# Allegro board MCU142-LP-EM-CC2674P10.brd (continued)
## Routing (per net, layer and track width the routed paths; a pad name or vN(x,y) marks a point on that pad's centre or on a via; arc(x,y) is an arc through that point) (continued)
XDS_BOARDID_SCL: length 16.1
  TOP w0.15: v1(11.83,80.05) U3.1
  L3 w0.15: v1(11.83,80.05) 19.88,80.05 22.84,83.01 J3.15
XDS_BOARDID_SDA: length 10.6
  TOP w0.15: U3.3 v1(13.73,80.86)
  L3 w0.15: v1(13.73,80.86) 18.26,80.86 20.3,82.9 J3.17
N3100073: length 1.4
  TOP w0.3: L14.1 C22.2 L13.2
N3100081: length 1.8
  TOP w0.3: C13.2 26.66,38.5 C23.2 26.66,38.98 26.66,38.98 L14.2
N3100583: length 9.2
  TOP w0.3: Z66.1 v1(27.25,34.5) ; v1(27.25,29.03) CR1.2 C15.2
  L2 w0.2: v1(27.25,34.5) v1(27.25,29.03)
N3100745: length 9.1
  TOP w0.15: C81.1 34.69,40.31 Y1.1 34,40.6 32.41,42.19 32.41,43.04 30.17,45.28 U1.8
N3100801: length 7
  TOP w0.15: C82.1 34.7,43.4 Y1.2 32.87,43.1 30.67,45.29 U1.9
N3100989: length 3.5
  TOP w0.25: C53.1 29.66,43.32 L53.2 29.14,43.85 L52.1 28.67,44.34 U1.5
N3100993: length 4.2
  TOP w0.3: Z61.1 Z60.2 27.26,22.04 27.25,22.05 C16.1
N3100997: length 3.1
  TOP w0.25: U1.6 29.17,44.63 L52.2 29.54,44.27 C61.1 30.12,43.72 L62.1
N3101171: length 1.5
  TOP w0.3: U1.23 33.4,51.45 33.88,51.93 C79.1
N3101223: length 6
  TOP w0.15: U1.47 25.1,46.95 24.92,46.78 22.68,46.78 21.48,45.57 C83.1 21.46,45.57
  TOP w0.3: Y2.1 21.46,45.57
N3101429: length 2.2
  TOP w0.3: A1.1 27.27,19.7 27.26,19.71 Z62.2 Z61.2
N3101449: length 6.8
  TOP w0.15: 20.81,48.09 Y2.3 21.44,48.53 21.85,48.53 23.3,47.07 24.75,47.07 25.13,47.45 U1.46
  TOP w0.3: C84.1 20.81,48.09
N3109742: length 12.7
  TOP w0.15: R71.2 19.15,53.05 19.62,53.05 v1(19.82,52.85)
  BOTTOM w0.15: v1(19.82,52.85) 18.52,51.55 11.6,51.55 10.39,52.76 J1.12
N3109836: length 12.3
  TOP w0.15: v1(19.92,50.85) 19.88,50.8 19.52,50.8 R72.2
  BOTTOM w0.15: J1.14 19.29,50.22 v1(19.92,50.85)
N3109894: length 22.9
  TOP w0.15: J2.13 47.33,52.42 47.33,63.15 44.98,65.5 40.42,65.5 39.57,66.35 R46.1
N3109960: length 25.8
  TOP w0.15: J2.15 46.46,50.75 46.46,59.71 46.45,59.72 46.45,62.16 43.41,65.2 39.27,65.2 38.12,66.35 R47.1
N3110034: length 29.1
  TOP w0.15: R48.1 36.67,66.35 38.2,64.82 42.38,64.82 44.7,62.5 44.7,62.48 45.67,61.51 45.67,60.41 45.59,60.32 45.59,49.08 J2.17
N3110086: length 32.1
  TOP w0.15: R49.1 35.22,66.35 37.58,63.99 41.63,63.99 44.34,61.28 44.34,47.79 J2.19
N3110356: length 2.9
  TOP w0.15: R14.2 9.55,35.93 P3.1
N3110380: length 2.9
  TOP w0.15: P3.3 15.8,36.01 R15.2
N3110768: length 1.4
  TOP w0.15: R56.1 SW1.4
N3110772: length 4.1
  TOP w0.15: SW2.3 54.4,70.18 54.55,70.03 54.55,68 55.45,67.1 R55.1
N3110876: length 1.8
  TOP w0.15: R15.1 14.63,34.75 14.63,34.75 CR3.2
N3110880: length 1.9
  TOP w0.15: CR2.2 10.87,34.75 10.87,34.75 R14.1
N3111246: length 1.9
  TOP w0.3: R12.1 45,40 C30.1 U4.8
N3111262: length 0.9
  TOP w0.15: R60.1 U4.7
N3111266: length 2.1
  TOP w0.15: R59.1 47.05,36.37 47.85,37.17 U4.3
N3215956: length 2.7
  TOP w0.15: 26.35,43.2 26.33,43.19
  TOP w0.25: U1.1 26.67,45.35 26.35,45.03 L11.1 L12.1 26.35,43.2 ; 26.33,43.19 C12.1
N3215974: length 2.7
  TOP w0.25: U1.2 27.17,45.25 26.91,44.99 L11.2 26.91,43.89 C21.2 26.92,43.88 L21.1
N3221205: length 1.3
  TOP w0.25: L21.2 26.92,42.53 26.65,42.25 26.65,42.2 ; 26.65,42.2 26.65,41.97 ; 26.65,42.2 26.32,42.52 C12.2
  TOP w0.3: L13.1 26.65,41.97
N3221963: length 0.9
  TOP w0.15: U2.3 27.3,37.07 27.29,37.07
  TOP w0.3: 27.29,37.07 C13.1
N3527855: length 14.3
  TOP w0.25: v1(28.54,42.41) 29.06,42.94 L53.1 29.8,42.4 29.82,42.4 30.3,41.91 C52.1
  TOP w0.3: v1(20.15,41.32) R7.1
  L3 w0.3: v1(20.15,41.32) 21.3,41.32 22.03,40.6 23.22,40.6 24.14,39.68 27.72,39.68 28.01,39.96 28.01,41.11 28.35,41.45 28.35,42.1 28.54,42.29 v1(28.54,42.41)
N3527991: length 2.7
  TOP w0.25: 31.2,41.02 L54.1 ; 30.54,42.44 30.73,42.25 31.2,42.25 ; 31.2,42.25 C62.1 ; 31.2,42.25 31.2,42.65 30.98,42.87 30.97,42.87
  TOP w0.3: C62.1 31.2,41.02
N3528063: length 1.4
  TOP w0.25: 31.2,39.78 C63.1
  TOP w0.3: C63.1 L55.1 ; L54.2 31.2,39.78
N3528075: length 1.4
  TOP w0.3: L55.2 C64.1 C56.1
N3806444: length 7.4
  TOP w0.3: C15.1 P5.1
N3819473: length 0.6
  TOP w0.3: C56.2 30.63,37.08 Z63-2.1
N3819482: length 1.2
  TOP w0.15: U2.1 28.55,37.07
  TOP w0.3: 28.55,37.07 Z64.2 29.44,37.07 Z63-2.2
N3821368: length 1.1
  TOP w0.15: U2.5 27.92,36.12 Z65.2
  TOP w0.3: Z65.2 Z66.2

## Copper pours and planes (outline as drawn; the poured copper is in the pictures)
GND on TOP (solid shape): 24.39,17.4 25.59,17.4 25.59,18.14 26.59,18.14 26.59,16.11 18.59,16.11 18.59,13.44 24.39,13.44 24.39,14.24 23.39,14.24 23.39,15.45 26.52,15.45 27.04,16.21 27.04,18.14 27.5,18.14 27.5,16.06 26.59,14.74 26.59,14.24 25.59,14.24 25.59,12.44 41.99,12.44 41.99,11.23 16.41,11.23 16.41,17.4 23.39,17.4 23.39,18.14 24.39,18.14
GND on TOP (solid shape): 9.45,81.1 9.45,76.1 3.2,76.1 3.07,76.44 2.75,76.6 2.15,76.6 1.83,76.44 1.7,76.1 1.25,76.1 0.69,77.29 0.5,78.6 0.5,81.1
GND on BOTTOM (solid shape): 9.45,76.1 1.25,76.1 0.69,77.3 0.5,78.6 0.5,81.1 9.45,81.1
GND on TOP: 57,88.63 57.71,88.34 58,87.63 58,78.6 57.74,77.1 57.01,75.76 55.8,72.3 57.01,68.84 57.74,67.5 58,66 58,19.65 57.56,18.59 56.5,18.15 2,18.15 0.94,18.59 0.5,19.65 0.5,66 0.76,67.5 1.49,68.84 2.7,72.3 1.49,75.76 0.76,77.1 0.5,78.6 0.5,87.63 0.79,88.34 1.5,88.63 ; 17 cut-outs
GND on BOTTOM: 56.95,88.62 57.66,88.33 57.95,87.62 57.95,77.93 57.62,76.79 57.01,75.76 55.8,72.3 57.01,68.84 57.62,67.81 57.95,66.67 57.95,19.65 57.51,18.59 56.45,18.15 2,18.15 0.94,18.59 0.5,19.65 0.5,66 0.76,67.5 1.49,68.84 2.7,72.3 1.49,75.76 0.76,77.1 0.5,78.6 0.5,87.62 0.79,88.33 1.5,88.62 ; 2 cut-outs
GND on L2: 0.5,87.65 0.79,88.36 1.5,88.65 57,88.65 57.71,88.36 58,87.65 58,78.6 57.74,77.1 57.01,75.76 55.8,72.3 57.01,68.84 57.74,67.5 58,66 58,19.65 57.56,18.59 56.5,18.15 2,18.15 0.94,18.59 0.5,19.65 0.5,66 0.76,67.5 1.49,68.84 2.7,72.3 1.49,75.76 0.76,77.1 0.5,78.6 ; 2 cut-outs
GND on L3: 2,18.15 0.94,18.59 0.5,19.65 0.5,66 0.76,67.5 1.49,68.84 2.49,70.8 2.66,73 55.84,73 56.01,70.8 57.01,68.84 57.74,67.5 58,66 58,19.65 57.56,18.59 56.5,18.15 ; 9 cut-outs
VDDR on TOP: 26.62,57.6 28.82,57.6 29.62,56.8 29.62,55.65 27.95,55.65 27.7,55.4 27.45,55.4 27,55.85 27,56.3 27,56.3 26.62,56.67
VDDR on L3: 24.75,46 24.75,48.81 23.55,48.81 23.55,54.55 27.88,54.55 27.88,57.68 25.15,57.68 25.15,57.12 23.94,56.15 21.96,56.15 21.96,46
VDDS on TOP: 23.61,55.38 23.61,53.62 25,53.62 25,55.38
VDDS on TOP: 23.61,54.7 23.61,53.62 26.9,53.62 26.9,54.7
VDDS on L3: 23.62,54.4 23.62,48.94 25.65,48.94 25.65,54.4
WMCU_VDD on TOP: 23.02,57.55 23.02,55.73 25,55.73 25,57.55
WMCU_VDD on L3: 23.45,64.4 15.47,72.2 7.71,72.2 7.71,64.81 7,64.1 5.63,64.1 4.94,64.82 5.06,68.01 4.99,74.45 5,74.45 5,76.45 21.6,76.45 21.6,88.4 26.65,88.4 26.65,76.4 54.87,76.4 54.87,32.85 54.84,32.82 53.85,32.82 52.45,31.43 51.5,31.43 50.1,32.82 50.1,33.7 53.15,33.7 53.15,72.2 41.11,72.2 41.11,70.4 39.71,70.4 39.71,72.2 20.68,72.2 21.05,71.8 21.65,71.2 25,67.76 25,55.72 23.02,55.72 23.02,57.75 23.45,57.75 ; 1 cut-out

Small or netless copper shapes (teardrops, artwork), in the pictures only: 76 on TOP, 60 on BOTTOM, 50 on L3

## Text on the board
Ref Des/Silkscreen Bottom: J1 | 1 | 10 | 21 | 30 | J3 | J4 | 31 | 40 | 11 | 20 | J2 | DIO23 | DIO22 | DIO24 | DIO12 | DIO13 | DIO25 | DIO27 | DIO28 | DIO29 | DIO30 | DIO26 | DIO7 | DIO6 | DIO20 | DIO18 | BPRST | DIO9 | DIO8 | DIO19 | DIO11 | LPRST | DIO15 | DIO14 | DIO10 | DIO5 | DIO21 | TMS | TCK | DIO16 | DIO17
User.Comments: MCU142 | Rev. A | Milling tool 2.0 mm TYP | Rev | A | RTM Version | Description | Revisions | RED | AFTER THE PRESS | BOTTOM LAYER | 2024-12-05 | Date
Ref Des/Silkscreen Top: U3 | U1 | CR4 | J3 | P4 | U4 | J1 | 10 | 1 | 21 | 30 | J4 | 40 | 31 | 20 | 11 | J2 | DIO23 | DIO12 | DIO13 | DIO22 | DIO24 | DIO15 | BTN-1 | Red: | DIO6 | DIO25 | DIO26 | DIO27 | DIO28 | DIO29 | DIO30 | LEDs | Green: | DIO7 | Rx/Tx | CC-ANTENNA-DK | Mount for: | PA | Target In | LP-EM-CC2674P10 | Rev:A | DIO20 | DIO18 | BPRST | BTN-2 | DIO14 | MCU142 | DIO19 | DIO11 | LPRST | DIO9 | DIO8 | DIO21 | DIO5 | DIO10 | DIO16 | DIO17 | TMS | TCK | GND | 5V | 3V3 | RXD | TXD | SWO | nRST | TDO | TDI
XSECTION_CHART: L1: TOP CONDUCTOR - COPPER + PLATING 0.035 MM | *  DIELECTRIC - FR-4 0.175 MM (TOP PRIORITY) | L2: L2 PLANE - COPPER 0.035 MM | *  DIELECTRIC - FR-4 1.11 MM | L3: L3 PLANE - COPPER 0.035 MM | *  DIELECTRIC - FR-4 0.175 MM | L4: BOTTOM CONDUCTOR - COPPER + PLATING 0.035 MM | DESIGN CROSS SECTION CHART | ___________________________ | TOTAL THICKNESS SHOULD BE 1.6 MM AFTER THE PRESS
DIMENSION: V. SCORE
PAGE_OUTLINE: LP-EM-CC2674P10 | MCU142
User.27: FIGURE | FINISHED_SIZE | 0.2 | 1.05 | 1.1 | 3.2 | 0.899 | 1.8x0.8 | DRILL CHART: TOP to BOTTOM | ALL UNITS ARE IN MILLIMETERS | PLATED | NON-PLATED | QTY | 1095 | 70 | 1 | 4 | 2
